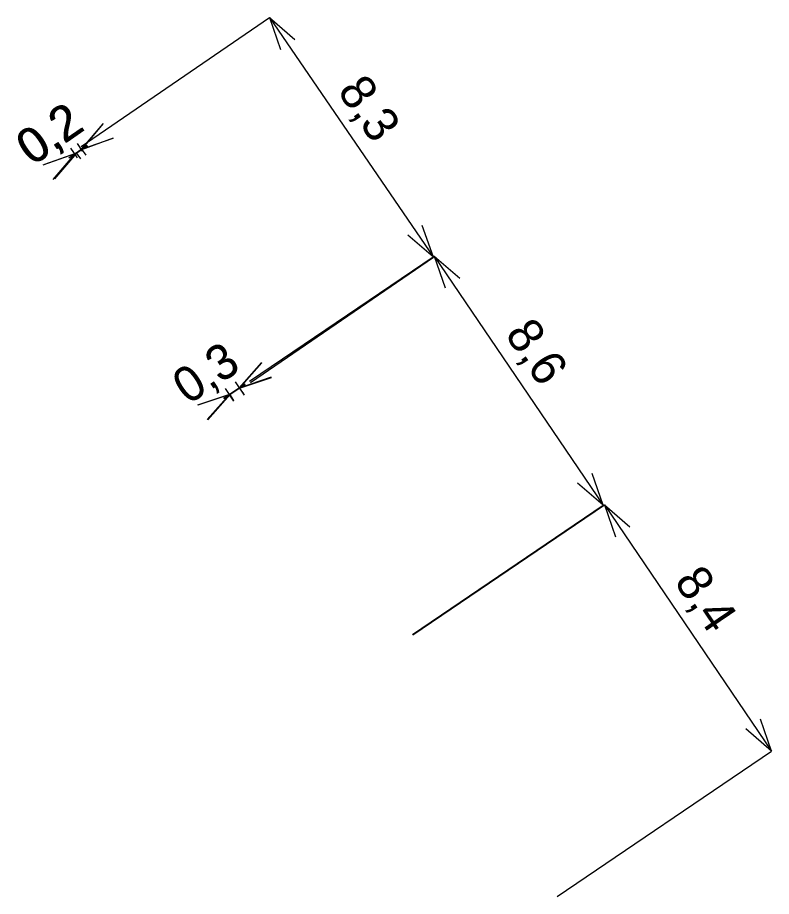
# Model space of a CAD drawing. Extents: x -739624 to -739416, y -1040979 to -1040677.
# Drawn here: x -739438 to -739416.5, y -1040979.49 to -1040954.42 of the extents above; entities that cross this region are included whole.
import ezdxf

# ---------------------------------------------------------------- set-up
doc = ezdxf.new("R2010")
doc.units = 0
doc.layers.add('Kota_VN', color=7, linetype='Continuous')

msp = doc.modelspace()

# ---------------------------------------------------------------- linework, layer by layer
at = {"layer": 'Kota_VN'}
for p, q in [((-739436.181, -1040958.1), (-739430.816, -1040954.424)), ((-739430.816, -1040954.424), (-739426.135, -1040961.256)), ((-739430.816, -1040954.424), (-739430.087, -1040955.049)), ((-739430.816, -1040954.424), (-739430.497, -1040955.33)), ((-739436.176, -1040958.181), (-739435.553, -1040957.45)), ((-739436.165, -1040958.183), (-739435.546, -1040957.449)), ((-739436.176, -1040958.181), (-739435.271, -1040957.859)), ((-739436.165, -1040958.183), (-739435.261, -1040957.856)), ((-739436.53, -1040958.425), (-739436.012, -1040958.067)), ((-739436.484, -1040958.405), (-739436.001, -1040958.068)), ((-739436.289, -1040958.422), (-739436.479, -1040958.147)), ((-739436.143, -1040958.229), (-739436.29, -1040958.016)), ((-739436.171, -1040958.175), (-739436.05, -1040958.347)), ((-739436.366, -1040958.311), (-739437.271, -1040958.633)), ((-739436.32, -1040958.291), (-739437.224, -1040958.618)), ((-739436.366, -1040958.311), (-739436.989, -1040959.042)), ((-739436.32, -1040958.291), (-739436.939, -1040959.025)), ((-739436.326, -1040958.283), (-739436.206, -1040958.455)), ((-739426.135, -1040961.256), (-739426.454, -1040960.35)), ((-739426.135, -1040961.256), (-739426.864, -1040960.631)), ((-739431.381, -1040964.795), (-739426.113, -1040961.225)), ((-739431.356, -1040964.833), (-739426.135, -1040961.256)), ((-739426.113, -1040961.225), (-739421.299, -1040968.33)), ((-739426.113, -1040961.225), (-739425.387, -1040961.854)), ((-739426.113, -1040961.225), (-739425.799, -1040962.133)), ((-739431.669, -1040964.978), (-739431.034, -1040964.257)), ((-739431.669, -1040964.991), (-739431.033, -1040964.271)), ((-739431.669, -1040964.978), (-739430.759, -1040964.67)), ((-739431.669, -1040964.991), (-739430.758, -1040964.686)), ((-739432.122, -1040965.28), (-739431.503, -1040964.867)), ((-739432.111, -1040965.284), (-739431.502, -1040964.88)), ((-739431.526, -1040965.193), (-739431.78, -1040964.812)), ((-739431.956, -1040965.169), (-739432.866, -1040965.477)), ((-739431.944, -1040965.173), (-739432.855, -1040965.478)), ((-739431.956, -1040965.169), (-739432.591, -1040965.89)), ((-739431.944, -1040965.173), (-739432.58, -1040965.893)), ((-739431.828, -1040965.361), (-739432.067, -1040965.003)), ((-739431.95, -1040965.165), (-739431.834, -1040965.34)), ((-739431.675, -1040964.982), (-739431.558, -1040965.157)), ((-739421.299, -1040968.33), (-739421.613, -1040967.422)), ((-739421.299, -1040968.33), (-739422.025, -1040967.701)), ((-739426.736, -1040972.014), (-739421.299, -1040968.33)), ((-739426.727, -1040972.029), (-739421.261, -1040968.321)), ((-739421.261, -1040968.321), (-739416.499, -1040975.34)), ((-739421.261, -1040968.321), (-739420.535, -1040968.95)), ((-739421.261, -1040968.321), (-739420.946, -1040969.229)), ((-739416.499, -1040975.34), (-739416.814, -1040974.432)), ((-739416.499, -1040975.34), (-739417.225, -1040974.711)), ((-739422.61, -1040979.486), (-739416.499, -1040975.34))]:
    msp.add_line(p, q, dxfattribs=at)

# ---------------------------------------------------------------- texts
for s, rotation, p in [('8,3', 304.4185, (-739428.896, -1040956.52)), ('0,2', 34.5725, (-739437.59, -1040958.67)), ('0,2', 34.9001, (-739437.559, -1040958.668)), ('8,6', 304.1225, (-739424.119, -1040963.455)), ('0,3', 33.6901, (-739433.138, -1040965.477)), ('0,3', 33.5518, (-739433.134, -1040965.482)), ('8,4', 304.1526, (-739419.294, -1040970.508))]:
    msp.add_text(s, height=1, rotation=rotation, dxfattribs=at).set_placement(p)

doc.saveas('drawing.dxf')
